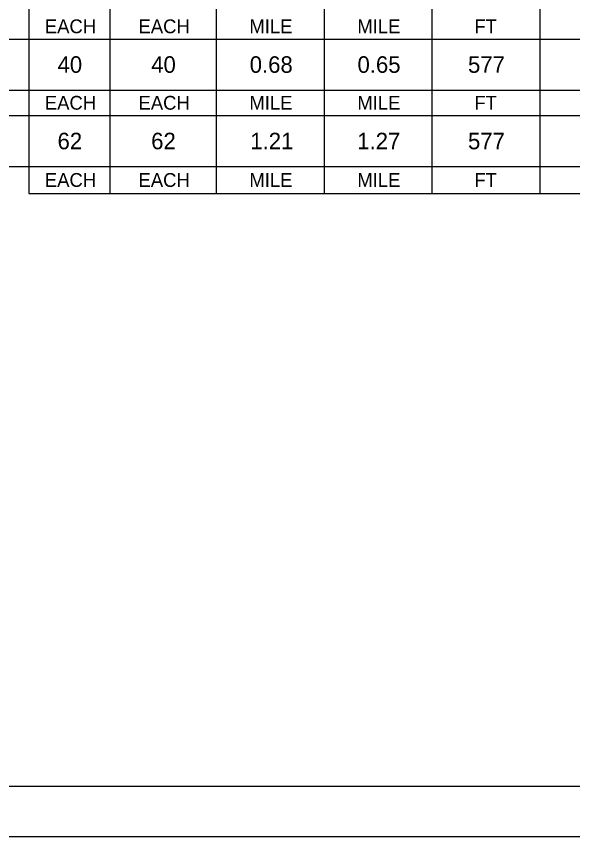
# Model space of a CAD drawing. Extents: x 0 to 34, y 0 to 22.
# Drawn here: x 22.79 to 28.36, y 0 to 8.21 of the extents above; entities that cross this region are included whole.
import ezdxf

# ---------------------------------------------------------------- set-up
doc = ezdxf.new("R2010")
doc.units = 0
for name, color, linetype in [('SH_Border', 7, 'Continuous'), ('SH_Cut_Line', 7, 'Continuous'), ('SH_Text', 7, 'Continuous')]:
    doc.layers.add(name, color=color, linetype=linetype)

msp = doc.modelspace()

# ---------------------------------------------------------------- linework, layer by layer
at = {"layer": 'SH_Border'}
msp.add_lwpolyline([(1.5, 21.5), (33.5, 21.5), (33.5, 0.5), (1.5, 0.5)], close=True, dxfattribs=at)
at = {"layer": 'SH_Cut_Line'}
msp.add_lwpolyline([(0, 0), (34, 0), (34, 22), (0, 22)], close=True, dxfattribs=at)
at = {"layer": 'SH_Text'}
for p, q in [((22.915, 18.69), (22.915, 6.435)), ((23.725, 18.69), (23.725, 6.435)), ((24.79, 18.69), (24.79, 6.435)), ((25.87, 18.69), (25.87, 6.435)), ((26.95, 18.69), (26.95, 6.435)), ((28.03, 18.69), (28.03, 6.435)), ((17.5, 7.98), (31, 7.98)), ((17.5, 7.47), (22.915, 7.47)), ((22.915, 7.47), (31, 7.47)), ((17.5, 7.215), (31, 7.215)), ((17.5, 6.705), (22.915, 6.705)), ((22.915, 6.705), (31, 6.705)), ((22.915, 6.435), (31, 6.435))]:
    msp.add_line(p, q, dxfattribs=at)

# ---------------------------------------------------------------- texts
for s, height, p in [('EACH', 0.138, (23.0759, 8.0385)), ('EACH', 0.138, (24.0134, 8.0385)), ('MILE', 0.138, (25.1236, 8.0385)), ('MILE', 0.138, (26.2036, 8.0385)), ('FT', 0.138, (27.3754, 8.0385)), ('40', 0.1656, (23.2027, 7.6422)), ('40', 0.1656, (24.1402, 7.6422)), ('0.68', 0.1656, (25.1263, 7.6422)), ('0.65', 0.1656, (26.2052, 7.6422)), ('577', 0.1656, (27.3115, 7.6422)), ('EACH', 0.138, (23.0759, 7.2735)), ('EACH', 0.138, (24.0134, 7.2735)), ('MILE', 0.138, (25.1236, 7.2735)), ('MILE', 0.138, (26.2036, 7.2735)), ('FT', 0.138, (27.3754, 7.2735)), ('62', 0.1656, (23.2027, 6.8772)), ('62', 0.1656, (24.1402, 6.8772)), ('1.21', 0.1656, (25.1323, 6.8772)), ('1.27', 0.1656, (26.2026, 6.8772)), ('577', 0.1656, (27.3115, 6.8772)), ('EACH', 0.138, (23.0759, 6.501)), ('EACH', 0.138, (24.0134, 6.501)), ('MILE', 0.138, (25.1236, 6.501)), ('MILE', 0.138, (26.2036, 6.501)), ('FT', 0.138, (27.3754, 6.501))]:
    msp.add_text(s, height=height, dxfattribs=at).set_placement(p)

doc.saveas('drawing.dxf')
